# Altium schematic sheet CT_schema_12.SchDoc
size 147 x 119 mm
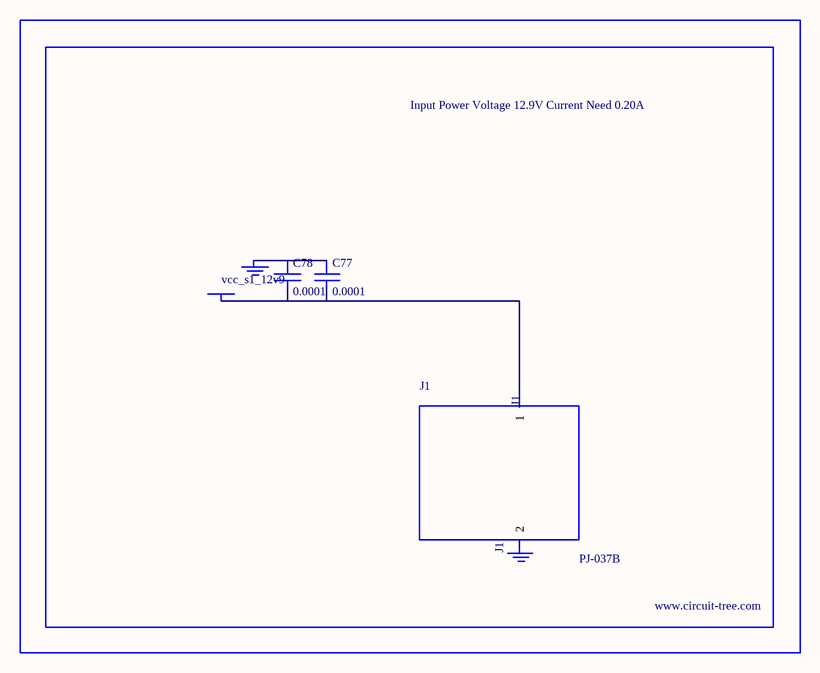
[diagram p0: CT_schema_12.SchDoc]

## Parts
BORDER11  (no value)
C77  0.0001  [EXV-9H]
C78  0.0001  [EXV-9H]
GND_INSTANCE_11_0  (no value)
GND_INSTANCE_11_1  (no value)
J1  PJ-037B  [PJ-037B_PACKAGE]
POWER_INSTANCE_11_0  vcc_s1_12v9

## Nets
NetC77_1: C77.1 C78.1 GND_INSTANCE_11_0.0(GND)
NetC77_2: C77.2 C78.2 J1.1 POWER_INSTANCE_11_0.0(PWR)

Not connected (* = marked no-connect by the designer): GND_INSTANCE_11_1 0(GND); J1 2

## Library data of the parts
BORDER11 = BORDER_PAGE11
C77 C78 = EDK107M035A9HAA
GND_INSTANCE_11_0 GND_INSTANCE_11_1 = GND
POWER_INSTANCE_11_0 = PWR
